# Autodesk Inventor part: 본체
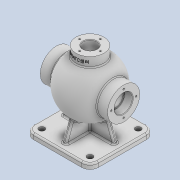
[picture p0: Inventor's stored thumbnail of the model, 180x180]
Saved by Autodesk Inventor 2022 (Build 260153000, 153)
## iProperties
Created: 2024-04
Part Number: 본체
Material: 일반
Document SubType Name: Modeling
Designer: Admin
Density: 1 g/cm^3
Appearance: 기본값
Author: Admin
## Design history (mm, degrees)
sketch "스케치1"
  geometry: L1 (-141.455, 0)-(183.523, 0); L2 (-65, 0)-(-65, 31); L3 (-65, 31)-(-44.215, 31); L4 (65, 0)-(65, 31); L5 (65, 31)-(44.215, 31); L6 (0, -10.8)-(0, 64.8) reference; A1 r 54 centre (0, 0) between (54, 0) and (-54, 0); 1 further point
  constraints: 10 end point, 5 point on line, 4 point on circle, 2 perpendicular, 2 vertical, 1 centre point, 1 coincident, 1 horizontal, 1 other
  dimensions: "d0" = 108 diameter of A1; "d1" = 62 diameter of L3 L1; "d2" = 62 diameter of L5 L1; "d3" = 130 distance between parallel lines of L4 L2
revolve "회전1" sketch "스케치1" stored, may be unused: angle "d4" = 90 deg
node "작업 평면1"
sketch "스케치2"
  geometry: L1 (62.5, 62.5)-(-62.5, 62.5); L2 (-62.5, 62.5)-(-62.5, -62.5); L3 (-62.5, -62.5)-(62.5, -62.5); L4 (62.5, -62.5)-(62.5, 62.5); L5 (62.5, 62.5)-(-62.5, -62.5); L6 (-62.5, 62.5)-(62.5, -62.5); 1 further point
  constraints: 12 end point, 2 midpoint, 2 parallel, 1 horizontal, 1 perpendicular
  dimensions: "d6" = 125 distance of L3.end L2.end; "d7" = 125 distance of L2.end L1.end
extrude "돌출1" join sketch "스케치2" distance "d8" = 10; taper "d9" = 0 deg
sketch "스케치3"
  geometry: L1 (-75, 62.5)-(-75, -62.5) reference; L2 (-75, -50.5)-(-25.518, -32.49); L3 (-25.518, -32.49)-(-25.518, 32.49); L4 (-25.518, 32.49)-(-75, 50.5); L5 (-85, -62.5)-(-75, -62.5) reference; L6 (-85, 62.5)-(-75, 62.5) reference; 1 further point
  constraints: 6 end point, 2 point on line, 1 parallel
  dimensions: "d10" = 12 distance from line of L5 L2.start; "d11" = 12 distance from line of L6 L4.end; "d12" = 20 deg angle of L5 L2; "d13" = 20 deg angle of L6 L4; "d14" = 49.48158 distance between parallel lines of L1 L3
extrude "돌출2" join sketch "스케치3" stored distance "d15" = 8; taper "d16" = 0 deg
sketch "스케치4"
  geometry: L1 (62.5, -75)-(-62.5, -75) reference; L2 (-50.5, -75)-(-32.494, -25.53); L3 (-32.494, -25.53)-(32.494, -25.53); L4 (32.494, -25.53)-(50.5, -75); L5 (-62.5, -85)-(-62.5, -75) reference; L6 (62.5, -85)-(62.5, -75) reference; 1 further point
  constraints: 6 end point, 2 point on line, 1 parallel
  dimensions: "d17" = 12 distance from line of L5 L2.start; "d18" = 12 distance from line of L6 L4.end; "d19" = 20 deg angle of L5 L2; "d20" = 20 deg angle of L6 L4; "d21" = 49.46992 distance between parallel lines of L1 L3
extrude "돌출3" join sketch "스케치4" stored distance "d22" = 8; taper "d23" = 0 deg
sketch "스케치5"
  geometry: L1 (-104.576, 0)-(135.869, 0); L2 (-65, -31)-(-65, 31) reference; L3 (-65, 0)-(-49, 0); L4 (-49, 0)-(-49, 17.5); L5 (-49, 17.5)-(-65, 17.5); L6 (-65, 17.5)-(-65, 0); L7 (-49, 0)-(-41.364, 0); L8 (-41.364, 0)-(-41.364, 15); L9 (-41.364, 15)-(-49, 15); L10 (-49, 15)-(-49, 0); L11 (65, -31)-(65, 31) reference; L12 (65, 0)-(49, 0); L13 (49, 0)-(49, 17.5); L14 (49, 17.5)-(65, 17.5); L15 (65, 17.5)-(65, 0); L16 (49, 0)-(41.364, 0); L17 (41.364, 0)-(41.364, 15); L18 (41.364, 15)-(49, 15); L19 (49, 15)-(49, 0); A1 r 44 centre (0, 0) between (41.364, 15) and (-41.364, 15); 7 further points
  constraints: 34 end point, 8 parallel, 5 horizontal, 4 perpendicular, 2 midpoint, 2 point on circle, 1 centre point, 1 coincident, 1 point on line
  dimensions: "d24" = 88 diameter of A1; "d25" = 35 diameter of L5 L1; "d26" = 30 diameter of L9 L1; "d27" = 35 diameter of L14 L1; "d28" = 30 diameter of L18 L1; "d29" = 16 distance between parallel lines of L2 L10; "d30" = 16 distance between parallel lines of L15 L19
revolve "회전2" sketch "스케치5" stored, may be unused: angle "d31" = 90 deg
sketch "스케치6"
  geometry: L1 (0, -112.8)-(0, 81.8) reference; 2 further points
  constraints: 1 point on line
  dimensions: "d32" = 24 distance of point (0, 0) point (0, 24)
hole "구멍1" sketch "스케치6" at (0, 24) diameter "d33" = 3.242; stored, may be unused: countersink angle "d37" = 90 deg, drill point angle "d39" = 118 deg; dims "d34" = 12, "d35" = 4, "d36" = 2, "d38" = 15
sketch "스케치7"
  geometry: L1 (0, -112.8)-(0, 81.8) reference; 2 further points
  constraints: 1 point on line
  dimensions: "d43" = 24 distance of point (0, 0) point (0, 24)
hole "구멍2" sketch "스케치7" at (0, 24) diameter "d44" = 3.242; stored, may be unused: countersink angle "d48" = 90 deg, drill point angle "d50" = 118 deg; dims "d45" = 12, "d46" = 4, "d47" = 2, "d49" = 15
node "작업 평면2"
sketch "스케치8"
  geometry: C1 r 27 at (0, 0); 1 further point
  constraints: 1 centre point, 1 coincident
  dimensions: "d55" = 54 diameter of C1
extrude "돌출4" join sketch "스케치8" stored distance "d56" = 8; taper "d57" = 0 deg
sketch "스케치9"
  geometry: C1 r 13 at (0, 0); 1 further point
  constraints: 1 centre point, 1 coincident
  dimensions: "d58" = 26 diameter of C1
extrude "돌출5" cut sketch "스케치9" stored distance "d59" = 10; taper "d60" = 0 deg
sketch "스케치10"
  geometry: L1 (0, 87.5)-(0, -87.5) reference; 2 further points
  constraints: 1 point on line
  dimensions: "d61" = 20 distance of point (0, 0) point (0, 20)
hole "구멍3" sketch "스케치10" at (0, 20) diameter "d62" = 3.242; stored, may be unused: countersink angle "d66" = 90 deg, drill point angle "d68" = 118 deg; dims "d63" = 9, "d64" = 4, "d65" = 2, "d67" = 11
fillet "모깎기1" dims "d72" = 16
sketch "스케치11"
  geometry: A1 r 16 centre (-46.5, 46.5) between (-46.5, 62.5) and (-62.5, 46.5) reference; A2 r 16 centre (46.5, 46.5) between (62.5, 46.5) and (46.5, 62.5) reference; A3 r 16 centre (46.5, -46.5) between (46.5, -62.5) and (62.5, -46.5) reference; A4 r 16 centre (-46.5, -46.5) between (-62.5, -46.5) and (-46.5, -62.5) reference; 5 further points
  constraints: 4 coincident
hole "구멍4" sketch "스케치11" at (-46.5, 46.5), (46.5, 46.5), (46.5, -46.5), (-46.5, -46.5) diameter "d73" = 11; stored, may be unused: countersink angle "d77" = 90 deg, drill point angle "d79" = 118 deg; dims "d74" = 9, "d75" = 4, "d76" = 2, "d78" = 11
node "작업 평면3"
sketch "스케치12"
  geometry: L1 (-27, 65)-(27, 65) reference; L2 (-27, 65)-(-27, 46.765) reference; 2 further points
  constraints: 1 other
  dimensions: "d81" = 9 distance from line of L1 point (0, 56); "d82" = 27 distance from line of L2 point (0, 56)
feature "엠보싱1" sketch "스케치12" dims "d83" = 0.5, "d84" = 0
fillet "모깎기2" dims "d85" = 0.6
fillet "모깎기3" dims "d86" = 3
fillet "모깎기4" dims "d87" = 3
fillet "모깎기5" dims "d88" = 3
chamfer "모따기1" distance "d89" = 1; stored, may be unused: second distance "d90" = 2, angle "d91" = 45 deg
node "솔리드1"
pattern_circular "원형 패턴1" dims angle "d41" = 360 deg
pattern_circular "원형 패턴2" dims angle "d52" = 360 deg
pattern_circular "원형 패턴3" dims angle "d70" = 360 deg
feature "A9D066F2-1C7D-4E18-AEED-F7BC21143FA4" dims "d73" = 11, "d74" = 9, "d75" = 4, "d76" = 2, "d77" = 90 deg, "d78" = 11, "d79" = 118 deg
other parameters: "d5" = -85, "d80" = 27
